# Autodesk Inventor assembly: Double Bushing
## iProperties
Shininess: 64.0
Length Units: 11269
Angle Units: 11279
Time Units: 11290
Mass Units: 11283
Length Display Precision: 3
Angle Display Precision: 2
Created: 2002-02
Part Number: Double Bushing
Document SubType Name: Assembly
Designer: ***
Density: 0.0
Volumn: 0.0
Area: 0.0
PropertySet Name: Model Information
Control State: 0
Master: False
Checked Out: False
Author: ***
